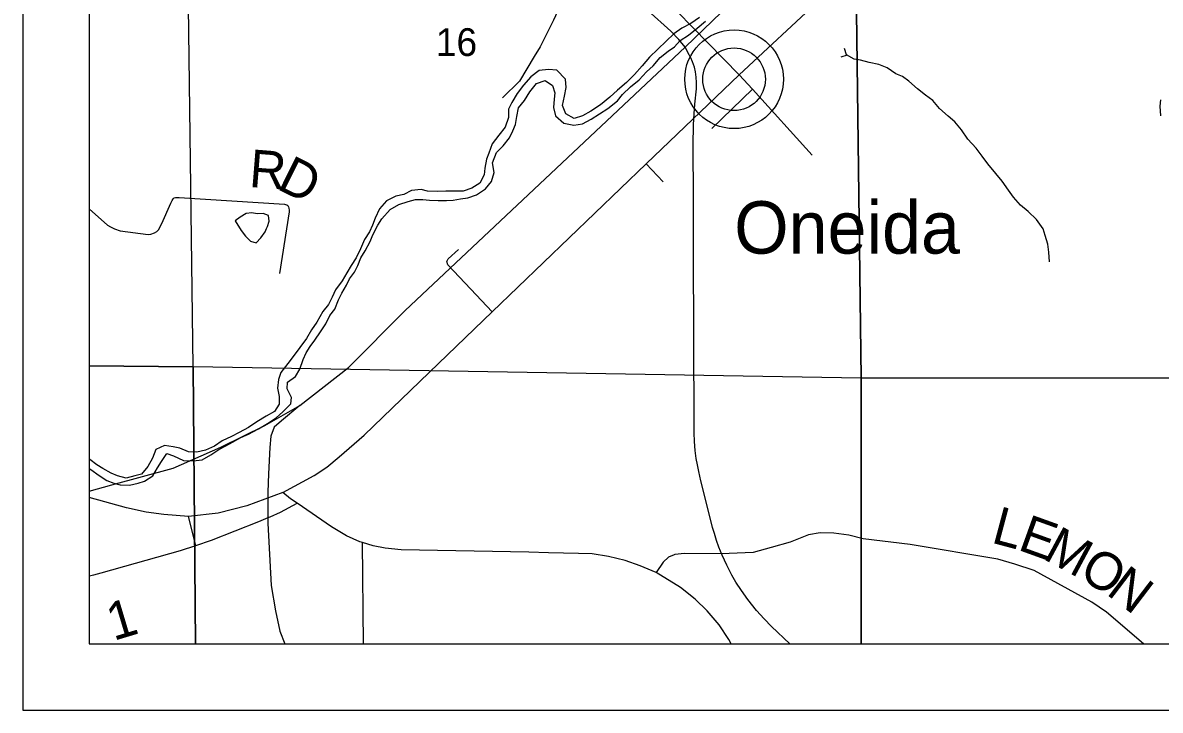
# Model space of a CAD drawing. Extents: x 0 to 34, y 0 to 22.
# Drawn here: x 2 to 3.716, y 14 to 15.037 of the extents above; entities that cross this region are included whole.
import ezdxf

# ---------------------------------------------------------------- set-up
doc = ezdxf.new("R2010")
doc.units = 0
for name, color, linetype in [('Default', 7, 'Continuous'), ('SH_Cut_Line', 7, 'Continuous'), ('SH_Data', 7, 'Continuous')]:
    doc.layers.add(name, color=color, linetype=linetype)

msp = doc.modelspace()

# ---------------------------------------------------------------- linework, layer by layer
at = {"layer": 'Default'}
for p, q in [((3.073, 14.9514), (3.073, 14.9514)), ((3.1006, 14.9366), (3.0393, 14.8772)), ((2.9661, 14.7966), (2.9405, 14.8241)), ((2.6417, 14.6808), (2.6571, 14.6949)), ((2.2613, 14.2482), (2.2501, 14.2923)), ((2.5138, 14.1), (2.5125, 14.2528))]:
    msp.add_line(p, q, dxfattribs=at)
for points in [[(2.1, 17.0156), (2.1, 14.1), (6.2892, 14.1), (6.2892, 14.18), (6.2889, 14.4906), (6.2926, 14.8972), (6.2959, 15.2705), (6.2922, 16.0152), (6.2871, 17.0188)], [(2.9993, 14.9996), (3.3253, 15.3142), (3.7288, 15.6994), (3.8497, 15.8071), (3.923, 15.8692), (3.9623, 15.9011), (4.0263, 15.9543), (4.1309, 16.0297)], [(3.0804, 14.9583), (2.9171, 15.1257), (2.9148, 15.1282), (2.9096, 15.1349), (2.9058, 15.1453), (2.9019, 15.1561), (2.901, 15.1653), (2.9004, 15.2236), (2.8999, 15.2317), (2.8989, 15.2384), (2.8976, 15.2437), (2.8947, 15.2486), (2.8894, 15.253), (2.8851, 15.2552), (2.8746, 15.2575), (2.8685, 15.2596)], [(2.8252, 15.0921), (2.8181, 15.0811), (2.8118, 15.0654), (2.8065, 15.0538), (2.8006, 15.0405), (2.7873, 15.0143), (2.7806, 15.0003), (2.7715, 14.9855), (2.7495, 14.9487), (2.7235, 14.9232)], [(3.1572, 14.1), (3.1295, 14.1261), (3.1184, 14.1377), (3.1067, 14.1506), (3.0939, 14.1671), (3.0843, 14.1804), (3.0758, 14.1932), (3.0698, 14.2038), (3.062, 14.2188), (3.0549, 14.2339), (3.0501, 14.2458), (3.0464, 14.2561), (3.0432, 14.2663), (3.0402, 14.2757), (3.0266, 14.3303), (3.0229, 14.3458), (3.0198, 14.3602), (3.0176, 14.3699), (3.016, 14.3796), (3.0145, 14.3917), (3.0133, 14.4052), (3.013, 14.4184), (3.0128, 14.4311), (3.0119, 14.692), (3.0117, 14.7721), (3.0115, 14.8519), (3.0117, 14.8826), (3.0126, 14.8994), (3.0137, 14.9138), (3.0162, 14.937), (3.0163, 14.9467), (3.0158, 14.9548), (3.0149, 14.9627), (3.0131, 14.9695), (3.0104, 14.9775), (3.0078, 14.9836), (3.0034, 14.9919), (2.9995, 14.9991), (2.9966, 15.0029), (2.9898, 15.0113), (2.9776, 15.0237), (2.9083, 15.0868)], [(2.3921, 14.3284), (2.4398, 14.3541), (2.4586, 14.3666), (2.4775, 14.3822), (2.5148, 14.4146), (2.6271, 14.5227), (2.708, 14.6008), (2.9405, 14.8241), (3.0804, 14.9583), (3.2029, 15.0723)], [(3.0206, 15.0447), (3.0079, 15.0354), (2.9944, 15.0287), (2.9821, 15.0201), (2.9705, 15.0089), (2.9579, 14.997), (2.9456, 14.9846), (2.9341, 14.9719), (2.9226, 14.9588), (2.9108, 14.9465), (2.8973, 14.9349), (2.8858, 14.9245), (2.8716, 14.9128), (2.8571, 14.9035), (2.8443, 14.8964), (2.8316, 14.8924), (2.8193, 14.8994), (2.8142, 14.9119), (2.8174, 14.926), (2.8198, 14.9389), (2.8185, 14.9518), (2.8058, 14.9652), (2.7929, 14.9661), (2.7789, 14.9644), (2.7666, 14.9551), (2.7555, 14.9427), (2.7459, 14.9297), (2.7378, 14.9166), (2.7327, 14.9063), (2.7325, 14.8938), (2.7279, 14.8793), (2.7182, 14.867), (2.7079, 14.8539), (2.7032, 14.8402), (2.6996, 14.8307), (2.6968, 14.8173), (2.6962, 14.8071), (2.6896, 14.7945), (2.6776, 14.7874), (2.6645, 14.7827), (2.6524, 14.7825), (2.6384, 14.7826), (2.6252, 14.7824), (2.6105, 14.7825), (2.601, 14.7854), (2.5866, 14.7836), (2.575, 14.7777), (2.5626, 14.7753), (2.5487, 14.7682), (2.538, 14.7559), (2.5314, 14.7421), (2.5274, 14.7314), (2.5231, 14.7215), (2.5157, 14.7096), (2.5095, 14.6955), (2.503, 14.6821), (2.4952, 14.6706), (2.4886, 14.6595), (2.4816, 14.6476), (2.472, 14.6338), (2.4666, 14.6227), (2.4611, 14.612), (2.4526, 14.6012), (2.4434, 14.5851), (2.4357, 14.5736), (2.4279, 14.5606), (2.418, 14.5472), (2.411, 14.5372), (2.3999, 14.5226), (2.3891, 14.5095), (2.3859, 14.4988), (2.3843, 14.4855), (2.3867, 14.473), (2.3869, 14.4613), (2.3796, 14.4506), (2.3672, 14.4435), (2.353, 14.4349), (2.3403, 14.4264), (2.3264, 14.4189), (2.3148, 14.413), (2.301, 14.406), (2.289, 14.3982), (2.2755, 14.3919), (2.2627, 14.389), (2.2502, 14.3896), (2.2369, 14.3954), (2.227, 14.3972), (2.2138, 14.3992), (2.2006, 14.3933), (2.1956, 14.3799), (2.1886, 14.3677), (2.179, 14.3561), (2.1692, 14.3533), (2.156, 14.3501), (2.1431, 14.3536)], [(2.93, 14.9506), (2.9411, 14.9626), (2.9508, 14.9718), (2.9615, 14.9841), (2.9734, 14.9938), (2.9831, 15.0004), (2.9917, 15.0101), (3.0044, 15.0179), (3.0171, 15.0283), (3.0301, 15.0391)], [(2.4179, 14.4597), (2.4913, 14.5167), (2.5767, 14.6025), (2.9993, 14.9996)], [(3.5487, 14.6762), (3.5477, 14.6906), (3.546, 14.7027), (3.542, 14.7159), (3.5392, 14.7261), (3.5291, 14.74), (3.5164, 14.7519), (3.5049, 14.7616), (3.4945, 14.7735), (3.4868, 14.784), (3.4771, 14.7979), (3.4678, 14.8095), (3.4559, 14.8241), (3.447, 14.8353), (3.4381, 14.8477), (3.4258, 14.8611), (3.4161, 14.875), (3.4057, 14.8873), (3.3961, 14.8959), (3.383, 14.9071), (3.3726, 14.9194), (3.3619, 14.9272), (3.3497, 14.9368), (3.3366, 14.9484), (3.327, 14.9554), (3.3171, 14.9598), (3.3041, 14.9687), (3.2912, 14.9738), (3.2768, 14.9769), (3.2639, 14.9801), (3.254, 14.9815), (3.2426, 14.9881), (3.2394, 14.9979)], [(3.2436, 14.9876), (3.2342, 14.9848)], [(2.1, 14.3645), (2.1044, 14.3621), (2.114, 14.355), (2.1266, 14.3465), (2.1376, 14.3425), (2.1471, 14.3397), (2.1608, 14.3395), (2.1739, 14.3424), (2.1837, 14.3456), (2.196, 14.3534), (2.2034, 14.3657), (2.2093, 14.3752), (2.2174, 14.3871), (2.2276, 14.3835), (2.2425, 14.3766), (2.2572, 14.376), (2.2705, 14.3774), (2.2835, 14.3852), (2.2959, 14.3934), (2.3064, 14.3985), (2.3165, 14.4044), (2.3292, 14.411), (2.3405, 14.4161), (2.3558, 14.4244), (2.3693, 14.4322), (2.382, 14.4407), (2.3924, 14.45), (2.4043, 14.462), (2.4053, 14.4718), (2.399, 14.4846), (2.3992, 14.4949), (2.4112, 14.5034), (2.4178, 14.5142), (2.4228, 14.529), (2.4276, 14.539), (2.4334, 14.5486), (2.4405, 14.5582), (2.4489, 14.5708), (2.4574, 14.5827), (2.4633, 14.595), (2.4706, 14.6049), (2.4761, 14.6187), (2.4812, 14.629), (2.4885, 14.6409), (2.4929, 14.6504), (2.5003, 14.6604), (2.5054, 14.6708), (2.5101, 14.6822), (2.5164, 14.6926), (2.5241, 14.7067), (2.5281, 14.717), (2.5354, 14.7316), (2.5416, 14.7412), (2.5543, 14.755), (2.5674, 14.7624), (2.5816, 14.7672), (2.5922, 14.7701), (2.6035, 14.7699), (2.6137, 14.7693), (2.6266, 14.7684), (2.639, 14.7686), (2.6492, 14.7691), (2.6602, 14.7712), (2.6715, 14.7725), (2.6846, 14.7769), (2.6981, 14.7863), (2.707, 14.7974), (2.7109, 14.8108), (2.7087, 14.8255), (2.7145, 14.8408), (2.7249, 14.8512), (2.7342, 14.8631), (2.7393, 14.8734), (2.7433, 14.883), (2.7453, 14.8952), (2.7478, 14.9085), (2.7567, 14.9192), (2.7647, 14.9323), (2.7751, 14.945), (2.7879, 14.9493), (2.799, 14.9419), (2.8026, 14.931), (2.8016, 14.9215), (2.8007, 14.9086), (2.8035, 14.8961), (2.8162, 14.8854), (2.831, 14.8822), (2.8442, 14.8843), (2.8573, 14.8914), (2.87, 14.8992), (2.8823, 14.9073), (2.8972, 14.919), (2.9046, 14.9286), (2.9169, 14.9401), (2.93, 14.9506)], [(3.0804, 14.9583), (3.1006, 14.9366), (3.1906, 14.8369)], [(3.7161, 14.9203), (3.7152, 14.9108), (3.7162, 14.8964)], [(2.1, 14.7558), (2.1279, 14.7315), (2.1325, 14.7289), (2.1382, 14.726), (2.147, 14.7228), (2.1892, 14.7175), (2.193, 14.7179), (2.1987, 14.7196), (2.2022, 14.7218), (2.2046, 14.7243), (2.2097, 14.7339), (2.2232, 14.7645), (2.2252, 14.7686), (2.2268, 14.771), (2.2286, 14.7724), (2.2303, 14.7731), (2.2316, 14.7733), (2.2361, 14.773)], [(2.2361, 14.773), (2.3946, 14.7629), (2.3963, 14.7627), (2.3981, 14.762), (2.3998, 14.7609), (2.401, 14.7593), (2.4016, 14.7569), (2.4019, 14.7542), (2.4018, 14.7515), (2.3872, 14.6583)], [(2.3678, 14.7262), (2.3693, 14.7296), (2.3718, 14.7372), (2.3709, 14.7459), (2.3625, 14.7492), (2.3538, 14.7487), (2.3455, 14.7501), (2.3368, 14.7488), (2.3282, 14.7433), (2.3204, 14.7379)], [(2.3204, 14.7379), (2.3293, 14.7233), (2.3359, 14.715), (2.3436, 14.7072), (2.3523, 14.7047), (2.3593, 14.7124), (2.3656, 14.7212), (2.3678, 14.7262)], [(2.708, 14.6008), (2.676, 14.635), (2.6413, 14.6714), (2.6396, 14.6767), (2.6417, 14.6808)], [(2.1, 14.3303), (2.1343, 14.3401), (2.2269, 14.3652), (2.2987, 14.3969), (2.3651, 14.4291), (2.4179, 14.4597)], [(2.4179, 14.4597), (2.3901, 14.4364), (2.379, 14.4268), (2.374, 14.4131), (2.3729, 14.3964), (2.3705, 14.3565), (2.3698, 14.329), (2.3695, 14.2821), (2.3749, 14.1882), (2.3811, 14.1497), (2.388, 14.1193), (2.3952, 14.1)], [(2.1431, 14.3536), (2.1336, 14.3573), (2.121, 14.3643), (2.1115, 14.3702), (2.1011, 14.378), (2.1, 14.3787)], [(2.3921, 14.3284), (2.338, 14.308), (2.2946, 14.2974), (2.2501, 14.2923)], [(2.7929, 14.2375), (2.7633, 14.2381), (2.5707, 14.2418), (2.5466, 14.2446), (2.5288, 14.2481), (2.5125, 14.2528), (2.5087, 14.2539), (2.4883, 14.2631), (2.4659, 14.2767), (2.4138, 14.3121), (2.404, 14.3189), (2.3921, 14.3284)], [(2.2501, 14.2923), (2.213, 14.2953), (2.1862, 14.2988), (2.1564, 14.305), (2.1, 14.3206)], [(2.3704, 14.2904), (2.3731, 14.2915), (2.3887, 14.2986), (2.4138, 14.3121)], [(2.1, 14.2026), (2.1073, 14.2042), (2.1182, 14.2071), (2.2378, 14.2409), (2.2613, 14.2482), (2.2847, 14.2566), (2.3559, 14.2844), (2.3704, 14.2904)], [(3.6907, 14.1), (3.6349, 14.1479), (3.6126, 14.1631), (3.5256, 14.2108), (3.4966, 14.2205), (3.471, 14.2276), (3.3388, 14.2499), (3.2679, 14.2584), (3.246, 14.2639), (3.2234, 14.2668), (3.2026, 14.2675), (3.1851, 14.2644), (3.1577, 14.2534), (3.129, 14.2456), (3.1019, 14.2379), (3.0537, 14.2357), (2.9982, 14.2365), (2.9837, 14.2348), (2.9828, 14.2344)], [(3.0687, 14.1), (3.0649, 14.1069), (3.0507, 14.129), (3.0326, 14.1501), (3.0142, 14.1677), (2.9921, 14.185), (2.9552, 14.2078), (2.9311, 14.2179), (2.9087, 14.226), (2.8835, 14.2317), (2.8587, 14.2359), (2.8383, 14.2365), (2.7929, 14.2375)], [(2.9828, 14.2344), (2.9739, 14.2306), (2.9662, 14.2234), (2.9552, 14.2078)]]:
    msp.add_lwpolyline(points, dxfattribs=at)
for points in [[(2.1, 15.5275), (2.1, 14.5191), (2.2573, 14.5177), (2.2442, 15.5273)], [(3.2514, 15.5272), (3.2648, 14.5009), (2.2573, 14.5177), (2.2442, 15.5273)], [(4.2566, 15.5062), (4.2629, 14.5006), (3.2648, 14.5009), (3.2514, 15.5272)], [(2.1, 14.5191), (2.1, 14.1), (2.2604, 14.1), (2.2573, 14.5177)], [(2.2604, 14.1), (3.2645, 14.1), (3.2648, 14.5009), (2.2573, 14.5177)], [(3.2645, 14.1), (4.2648, 14.1), (4.2629, 14.5006), (3.2648, 14.5009)]]:
    msp.add_lwpolyline(points, close=True, dxfattribs=at)
for radius in [0.0744, 0.0472]:
    msp.add_circle((3.073, 14.9514), radius, dxfattribs=at)
at = {"layer": 'SH_Cut_Line'}
msp.add_lwpolyline([(2.1, 17.0156), (2.1, 14.1), (8.9, 14.1), (8.9, 17.02)], dxfattribs=at)
at = {"layer": 'SH_Data'}
for p, q in [((2, 21), (2, 14)), ((2.1, 20.9), (2.1, 14.1)), ((2.1, 14.1), (8.9, 14.1)), ((2.1, 14.1), (2.1, 14.1)), ((2, 14), (9, 14))]:
    msp.add_line(p, q, dxfattribs=at)

# ---------------------------------------------------------------- texts
at = {"layer": 'Default'}
for s, height, rotation, p in [('16', 0.04186, 0, (2.6231, 14.9865)), ('R', 0.0568, 355.4953, (2.3404, 14.7892)), ('D', 0.0568, 333.549, (2.3815, 14.787)), ('Oneida', 0.07898, 0, (3.0731, 14.6885)), ('L', 0.0568, 345.0636, (3.4594, 14.2531)), ('E', 0.0568, 340.1894, (3.4993, 14.2425)), ('M', 0.0568, 331.7585, (3.5372, 14.229)), ('O', 0.0568, 329.7441, (3.5911, 14.2001)), ('N', 0.0568, 322.6653, (3.6327, 14.1759)), ('1', 0.0568, 16.6624, (2.1369, 14.1044))]:
    msp.add_text(s, height=height, rotation=rotation, dxfattribs=at).set_placement(p)

doc.saveas('drawing.dxf')
